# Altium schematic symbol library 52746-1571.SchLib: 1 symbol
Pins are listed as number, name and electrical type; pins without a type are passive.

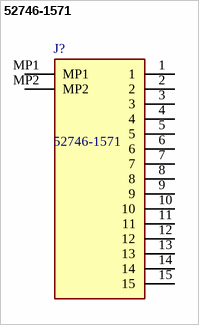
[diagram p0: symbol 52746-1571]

## 52746-1571
designator J?
Molex FFC/FPC SMT Series 0.5mm Pitch 15 Way 1 Row Right Angle SMT Female PCB Housing, Gold over Nickel Plated Contacts; Geometry.Height: 2.2mm
footprint 527461571
pins: 1, 2, 3, 4, 5, 6, 7, 8, 9, 10, 11, 12, 13, 14, 15, MP1, MP2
